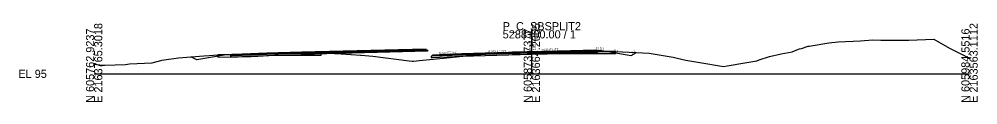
# Model space of a CAD drawing. Extents: x -26 to 1303, y -10 to 12033.
# Drawn here: x -25.7 to 302.8, y 4490.3 to 4517.8 of the extents above; entities that cross this region are included whole.
import ezdxf

# ---------------------------------------------------------------- set-up
doc = ezdxf.new("R2010")
doc.units = 0
for name, color, linetype in [('RD_GPK_XS_Cell', 7, 'Continuous'), ('RD_XS_Base', 7, 'Continuous'), ('RD_XS_ExGround', 7, 'Continuous'), ('RD_XS_ExPaveRet', 7, 'Continuous'), ('RD_XS_Greenside', 7, 'Continuous'), ('RD_XS_Pave', 7, 'Continuous'), ('RD_XS_PaveOvlay_CP', 7, 'Continuous'), ('RD_XS_TieSlope', 7, 'Continuous'), ('RD_XS_TX_Elev_EX', 7, 'Continuous'), ('RD_XS_TX_Elev_PR', 7, 'Continuous'), ('RD_XS_TX_ShdSlope', 7, 'Continuous'), ('RD_XS_TX_Slope', 7, 'Continuous')]:
    doc.layers.add(name, color=color, linetype=linetype)

msp = doc.modelspace()

# ---------------------------------------------------------------- linework, layer by layer
at = {"layer": 'RD_GPK_XS_Cell'}
for p, q in [((150, 4500), (150, 4515)), ((0, 4500), (150, 4500)), ((150, 4500), (300, 4500))]:
    msp.add_line(p, q, dxfattribs=at)
at = {"layer": 'RD_XS_Base'}
for p, q in [((71.22, 4507.13), (114.26, 4508.25)), ((114.26, 4507.75), (71.22, 4506.63)), ((95.22, 4507.75), (95.22, 4507.75)), ((95.22, 4507.75), (95.22, 4507.75)), ((113.76, 4508.23), (113.76, 4508.23)), ((114.26, 4508.25), (114.26, 4507.75)), ((114.26, 4508.21), (114.26, 4508.21)), ((150, 4507.23), (172, 4507.85)), ((162, 4507.57), (162, 4507.57)), ((162, 4507.57), (162, 4507.57)), ((172, 4507.85), (172, 4507.85)), ((172.5, 4507.86), (172.5, 4507.36)), ((172.5, 4507.83), (172.5, 4507.83)), ((46.86, 4506.32), (46.72, 4506.32)), ((46.72, 4506.32), (46.72, 4505.96)), ((46.72, 4505.96), (46.72, 4505.82)), ((46.72, 4505.82), (46.86, 4505.82)), ((47.22, 4506.34), (46.86, 4506.32)), ((46.86, 4505.82), (47.22, 4505.84)), ((50.78, 4506.48), (47.22, 4506.34)), ((47.22, 4505.84), (50.78, 4505.98)), ((59.22, 4506.82), (50.78, 4506.48)), ((50.78, 4505.98), (59.22, 4506.32)), ((63.02, 4506.92), (59.22, 4506.82)), ((59.22, 4506.32), (63.02, 4506.42)), ((71.22, 4507.13), (63.02, 4506.92)), ((63.02, 4506.42), (71.22, 4506.63)), ((71.22, 4506.63), (71.22, 4507.29)), ((71.22, 4507.29), (71.22, 4507.29)), ((71.22, 4507.29), (71.22, 4507.29)), ((71.22, 4507.29), (71.22, 4507.13)), ((71.22, 4507.13), (71.22, 4507.13)), ((71.22, 4506.63), (71.22, 4507.13)), ((71.22, 4507.13), (71.22, 4507.13)), ((71.22, 4507.13), (71.22, 4507.13)), ((71.22, 4506.63), (71.22, 4506.63)), ((95.22, 4507.25), (95.22, 4507.25)), ((95.22, 4507.25), (95.22, 4507.25)), ((116, 4506.16), (115.5, 4506.14)), ((115.5, 4506.14), (115.5, 4506.14)), ((115.5, 4506.14), (115.5, 4505.64)), ((115.5, 4505.64), (116, 4505.66)), ((126, 4506.56), (116, 4506.16)), ((116, 4506.16), (116, 4506.16)), ((116, 4505.66), (126, 4506.06)), ((116, 4505.66), (116, 4505.66)), ((150, 4507.23), (126, 4506.56)), ((126, 4506.06), (150, 4506.73)), ((126, 4506.56), (126, 4506.56)), ((126, 4506.06), (126, 4506.06)), ((150, 4506.73), (150, 4507.39)), ((150, 4507.39), (150, 4507.39)), ((150, 4507.39), (150, 4507.39)), ((150, 4507.39), (150, 4507.23)), ((172.5, 4507.36), (150, 4506.73)), ((150, 4507.23), (150, 4507.23)), ((150, 4506.73), (150, 4507.23)), ((150, 4507.23), (150, 4507.23)), ((150, 4507.23), (150, 4507.23)), ((150, 4506.73), (150, 4506.73)), ((162, 4507.07), (162, 4507.07)), ((162, 4507.07), (162, 4507.07))]:
    msp.add_line(p, q, dxfattribs=at)
at = {"layer": 'RD_XS_ExGround'}
msp.add_lwpolyline([(0, 4503.33), (2.82, 4503.03), (3.7, 4503.02), (10.75, 4503.22), (12.11, 4503.4), (19.93, 4503.83), (22.82, 4504.6), (23.17, 4504.67), (28.95, 4505.5), (37.57, 4506.17), (39.45, 4506.28), (42.42, 4506.49), (49.38, 4506.66), (54.94, 4506.8), (56.15, 4506.83), (61.9, 4507.15), (64.07, 4507.19), (72.13, 4507.2), (77.83, 4507.23), (84.68, 4506.85), (91.26, 4506.44), (91.46, 4506.44), (95.52, 4506.11), (108.01, 4504.47), (109, 4504.34), (109.46, 4504.38), (111.51, 4504.58), (120.85, 4505.51), (124.18, 4505.83), (130.73, 4506.49), (132.53, 4506.63), (143.36, 4507.42), (148.45, 4507.55), (152.06, 4507.62), (155.31, 4507.66), (158.63, 4507.75), (159.06, 4507.78), (161.14, 4507.75), (169.9, 4507.74), (178.73, 4507.72), (185.6, 4507.32), (190.19, 4507.06), (198.48, 4505.69), (199.35, 4505.54), (199.79, 4505.44), (202.73, 4504.72), (207.58, 4503.94), (215.63, 4502.58), (216.99, 4502.7), (222.95, 4503.76), (227.11, 4504.52), (227.95, 4504.78), (231.41, 4506.01), (235.45, 4506.9), (239.24, 4507.57), (241.42, 4508.47), (241.77, 4508.57), (242.39, 4508.78), (244.74, 4509.55), (245.07, 4509.55), (251.78, 4510.62), (254.95, 4511.07), (262.63, 4511.4), (266.88, 4511.74), (269.59, 4511.55), (275.51, 4511.54), (279.25, 4511.63), (287.74, 4511.97), (293.12, 4508.83), (296.79, 4507.01), (299.05, 4505.84), (300, 4505.27)], dxfattribs=at)
at = {"layer": 'RD_XS_ExPaveRet'}
for points in [[(178.73, 4507.72), (178.73, 4507.72), (169.9, 4507.74), (169.9, 4507.74), (161.14, 4507.75), (159.06, 4507.78), (159.06, 4507.78), (158.63, 4507.75), (158.63, 4507.75), (158.63, 4507.75), (155.31, 4507.66), (155.31, 4507.66), (152.06, 4507.62), (152.06, 4507.62), (148.45, 4507.55), (148.45, 4507.55), (143.37, 4507.42), (143.37, 4507.42), (143.37, 4506.67), (148.45, 4506.8), (148.45, 4506.8), (152.06, 4506.87), (152.06, 4506.87), (155.31, 4506.91), (155.31, 4506.91), (158.63, 4507), (158.63, 4507), (158.63, 4507), (159.06, 4507.03), (159.06, 4507.03), (161.14, 4507), (169.9, 4506.99), (169.9, 4506.99), (178.73, 4506.97), (178.73, 4506.97), (178.73, 4506.97), (178.73, 4507.72), (178.73, 4507.72), (178.73, 4507.72)], [(178.73, 4507.72), (169.9, 4507.74), (161.14, 4507.75), (159.06, 4507.78), (158.63, 4507.75), (155.31, 4507.66), (152.06, 4507.62), (148.45, 4507.55), (143.37, 4507.42), (143.37, 4506.67), (148.45, 4506.8), (152.06, 4506.87), (155.31, 4506.91), (158.63, 4507), (159.06, 4507.03), (161.14, 4507), (169.9, 4506.99), (178.73, 4506.97), (178.73, 4506.97), (178.73, 4507.72), (178.73, 4507.72)], [(77.83, 4507.23), (76.19, 4507.22), (72.13, 4507.2), (67.68, 4507.19), (64.07, 4507.19), (62.92, 4507.17), (61.9, 4507.15), (59.82, 4507.03), (56.15, 4506.83), (55.17, 4506.81), (54.94, 4506.8), (53.83, 4506.77), (49.38, 4506.66), (42.42, 4506.49), (42.42, 4506.49), (42.42, 4506.24), (42.42, 4505.74), (42.42, 4505.74), (49.38, 4505.91), (53.83, 4506.02), (54.94, 4506.05), (55.17, 4506.06), (56.15, 4506.08), (59.82, 4506.28), (61.9, 4506.4), (62.92, 4506.42), (64.07, 4506.44), (67.68, 4506.44), (72.13, 4506.45), (76.19, 4506.47), (77.83, 4506.48), (77.83, 4506.48), (77.83, 4506.48), (77.83, 4506.84), (77.83, 4507.23), (77.83, 4507.23), (77.83, 4507.23)], [(77.83, 4507.23), (76.19, 4507.22), (72.13, 4507.2), (67.68, 4507.19), (64.07, 4507.19), (62.92, 4507.17), (61.9, 4507.15), (59.82, 4507.03), (56.15, 4506.83), (55.17, 4506.81), (54.94, 4506.8), (53.83, 4506.77), (49.38, 4506.66), (42.42, 4506.49), (42.42, 4506.49), (42.42, 4506.24), (42.42, 4505.74), (42.42, 4505.74), (49.38, 4505.91), (53.83, 4506.02), (54.94, 4506.05), (55.17, 4506.06), (56.15, 4506.08), (59.82, 4506.28), (61.9, 4506.4), (62.92, 4506.42), (64.07, 4506.44), (67.68, 4506.44), (72.13, 4506.45), (76.19, 4506.47), (77.83, 4506.48), (77.83, 4506.48), (77.83, 4506.48), (77.83, 4506.84), (77.83, 4507.23), (77.83, 4507.23), (77.83, 4507.23)]]:
    msp.add_lwpolyline(points, dxfattribs=at)
at = {"layer": 'RD_XS_Greenside'}
for p, q in [((174, 4508), (184, 4506.34)), ((35.22, 4504.83), (33.19, 4505.84)), ((45.22, 4506.5), (35.22, 4504.83)), ((184, 4506.34), (185.92, 4507.3))]:
    msp.add_line(p, q, dxfattribs=at)
at = {"layer": 'RD_XS_Pave'}
for p, q in [((113.76, 4508.55), (71.22, 4507.45)), ((113.76, 4508.39), (71.22, 4507.29)), ((71.22, 4507.29), (113.76, 4508.39)), ((71.22, 4507.13), (113.76, 4508.23)), ((95.22, 4508.07), (95.22, 4508.07)), ((95.22, 4508.07), (95.22, 4508.07)), ((95.22, 4507.91), (95.22, 4507.91)), ((95.22, 4507.91), (95.22, 4507.91)), ((95.22, 4507.91), (95.22, 4507.91)), ((95.22, 4507.91), (95.22, 4507.91)), ((95.22, 4507.75), (95.22, 4507.75)), ((95.22, 4507.75), (95.22, 4507.75)), ((113.76, 4508.39), (113.76, 4508.55)), ((113.76, 4508.55), (113.76, 4508.55)), ((113.76, 4508.23), (113.76, 4508.39)), ((113.76, 4508.39), (113.76, 4508.39)), ((150, 4507.55), (126, 4506.88)), ((172, 4508.16), (150, 4507.55)), ((172, 4508.01), (150, 4507.39)), ((150, 4507.39), (172, 4508.01)), ((150, 4507.23), (172.5, 4507.86)), ((150, 4507.55), (150, 4507.55)), ((162, 4507.88), (162, 4507.88)), ((162, 4507.88), (162, 4507.88)), ((162, 4507.73), (162, 4507.73)), ((162, 4507.73), (162, 4507.73)), ((162, 4507.73), (162, 4507.73)), ((162, 4507.73), (162, 4507.73)), ((162, 4507.57), (162, 4507.57)), ((162, 4507.57), (162, 4507.57)), ((172, 4508.01), (172, 4508.16)), ((172, 4508.16), (172, 4508.16)), ((172, 4507.85), (172, 4508.01)), ((172, 4508.01), (172, 4508.01)), ((50.78, 4506.8), (47.22, 4506.66)), ((47.22, 4506.66), (47.22, 4506.54)), ((47.22, 4506.5), (50.78, 4506.64)), ((50.78, 4506.64), (47.22, 4506.5)), ((47.22, 4506.54), (47.22, 4506.5)), ((47.22, 4506.5), (47.22, 4506.38)), ((47.22, 4506.34), (50.78, 4506.48)), ((47.22, 4506.38), (47.22, 4506.34)), ((59.22, 4507.14), (50.78, 4506.8)), ((50.78, 4506.64), (59.22, 4506.98)), ((59.22, 4506.98), (50.78, 4506.64)), ((50.78, 4506.48), (59.22, 4506.82)), ((63.02, 4507.23), (59.22, 4507.14)), ((59.22, 4506.98), (63.02, 4507.07)), ((63.02, 4507.07), (59.22, 4506.98)), ((59.22, 4506.82), (63.02, 4506.92)), ((71.22, 4507.45), (63.02, 4507.23)), ((63.02, 4507.07), (71.22, 4507.29)), ((71.22, 4507.29), (63.02, 4507.07)), ((63.02, 4506.92), (71.22, 4507.13)), ((71.22, 4507.45), (71.22, 4507.45)), ((71.22, 4507.29), (71.22, 4507.29)), ((71.22, 4507.29), (71.22, 4507.29)), ((71.22, 4507.29), (71.22, 4507.13)), ((71.22, 4507.29), (71.22, 4507.29)), ((71.22, 4507.13), (71.22, 4507.29)), ((71.22, 4507.29), (71.22, 4507.29)), ((71.22, 4507.29), (71.22, 4507.29)), ((71.22, 4507.13), (71.22, 4507.13)), ((71.22, 4507.13), (71.22, 4507.13)), ((126, 4506.88), (116, 4506.48)), ((116, 4506.32), (126, 4506.72)), ((126, 4506.72), (116, 4506.32)), ((116, 4506.16), (126, 4506.56)), ((116, 4506.48), (116, 4506.48)), ((116, 4506.48), (116, 4506.32)), ((116, 4506.32), (116, 4506.32)), ((116, 4506.32), (116, 4506.16)), ((126, 4506.72), (150, 4507.39)), ((150, 4507.39), (126, 4506.72)), ((126, 4506.56), (150, 4507.23)), ((126, 4506.88), (126, 4506.88)), ((126, 4506.72), (126, 4506.72)), ((126, 4506.72), (126, 4506.72)), ((126, 4506.56), (126, 4506.56)), ((150, 4507.39), (150, 4507.39)), ((150, 4507.39), (150, 4507.39)), ((150, 4507.39), (150, 4507.23)), ((150, 4507.39), (150, 4507.39)), ((150, 4507.23), (150, 4507.39)), ((150, 4507.39), (150, 4507.39)), ((150, 4507.39), (150, 4507.39)), ((150, 4507.23), (150, 4507.23)), ((150, 4507.23), (150, 4507.23))]:
    msp.add_line(p, q, dxfattribs=at)
at = {"layer": 'RD_XS_PaveOvlay_CP'}
for p, q in [((113.76, 4508.55), (71.22, 4507.45)), ((95.22, 4508.07), (95.22, 4508.07)), ((95.22, 4508.07), (95.22, 4508.07)), ((150, 4507.55), (126, 4506.88)), ((172, 4508.16), (150, 4507.55)), ((150, 4507.55), (150, 4507.55)), ((162, 4507.88), (162, 4507.88)), ((162, 4507.88), (162, 4507.88)), ((50.78, 4506.8), (47.22, 4506.66)), ((59.22, 4507.14), (50.78, 4506.8)), ((63.02, 4507.23), (59.22, 4507.14)), ((71.22, 4507.45), (63.02, 4507.23)), ((71.22, 4507.45), (71.22, 4507.45)), ((126, 4506.88), (116, 4506.48)), ((126, 4506.88), (126, 4506.88))]:
    msp.add_line(p, q, dxfattribs=at)
at = {"layer": 'RD_XS_TieSlope'}
for p, q in [((172, 4508.16), (174, 4508)), ((47.22, 4506.66), (45.22, 4506.5))]:
    msp.add_line(p, q, dxfattribs=at)

# ---------------------------------------------------------------- texts
at = {"layer": 'RD_GPK_XS_Cell'}
for s, p in [('P_C_SBSPLIT2', (140, 4515)), ('5288+00.00 / 1', (140, 4512.2)), ('EL 95', (-26, 4498.6))]:
    msp.add_text(s, height=2.8, dxfattribs=at).set_placement(p)
for s, p in [('E 2163664.2065', (152.8, 4490)), ('N 605762.9237', (0, 4490)), ('E 2163765.3018', (2.8, 4490)), ('N 605873.7377', (150, 4490)), ('N 605984.5516', (300, 4490)), ('E 2163563.1112', (302.8, 4490))]:
    msp.add_text(s, height=2.8, rotation=90, dxfattribs=at).set_placement(p)
at = {"layer": 'RD_XS_TX_Elev_EX'}
msp.add_text('102.58', height=0.6, rotation=90, dxfattribs=at).set_placement((149.6, 4508.47))
at = {"layer": 'RD_XS_TX_Elev_PR'}
msp.add_text('102.55', height=1, rotation=90, dxfattribs=at).set_placement((151.33, 4508.07))
at = {"layer": 'RD_XS_TX_ShdSlope'}
msp.add_text('12.5:1', height=0.75, rotation=355.4261, dxfattribs=at).set_placement((171.84, 4508.5))
at = {"layer": 'RD_XS_TX_Slope'}
for s, rotation, p in [('0.040 FT./FT.', 2.2906, (118.15, 4506.71)), ('0.030 FT./FT.', 1.7184, (135.16, 4507.29)), ('0.030 FT./FT.', 1.7184, (153.16, 4507.83)), ('6:1', 350.5358, (178.13, 4507.71)), ('2:1', 26.5651, (184.35, 4506.94))]:
    msp.add_text(s, height=0.75, rotation=rotation, dxfattribs=at).set_placement(p)

doc.saveas('drawing.dxf')
